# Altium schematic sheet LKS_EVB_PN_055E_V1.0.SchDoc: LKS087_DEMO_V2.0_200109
size A4; Revision: V1.0; SheetNumber: 1; SheetTotal: 1
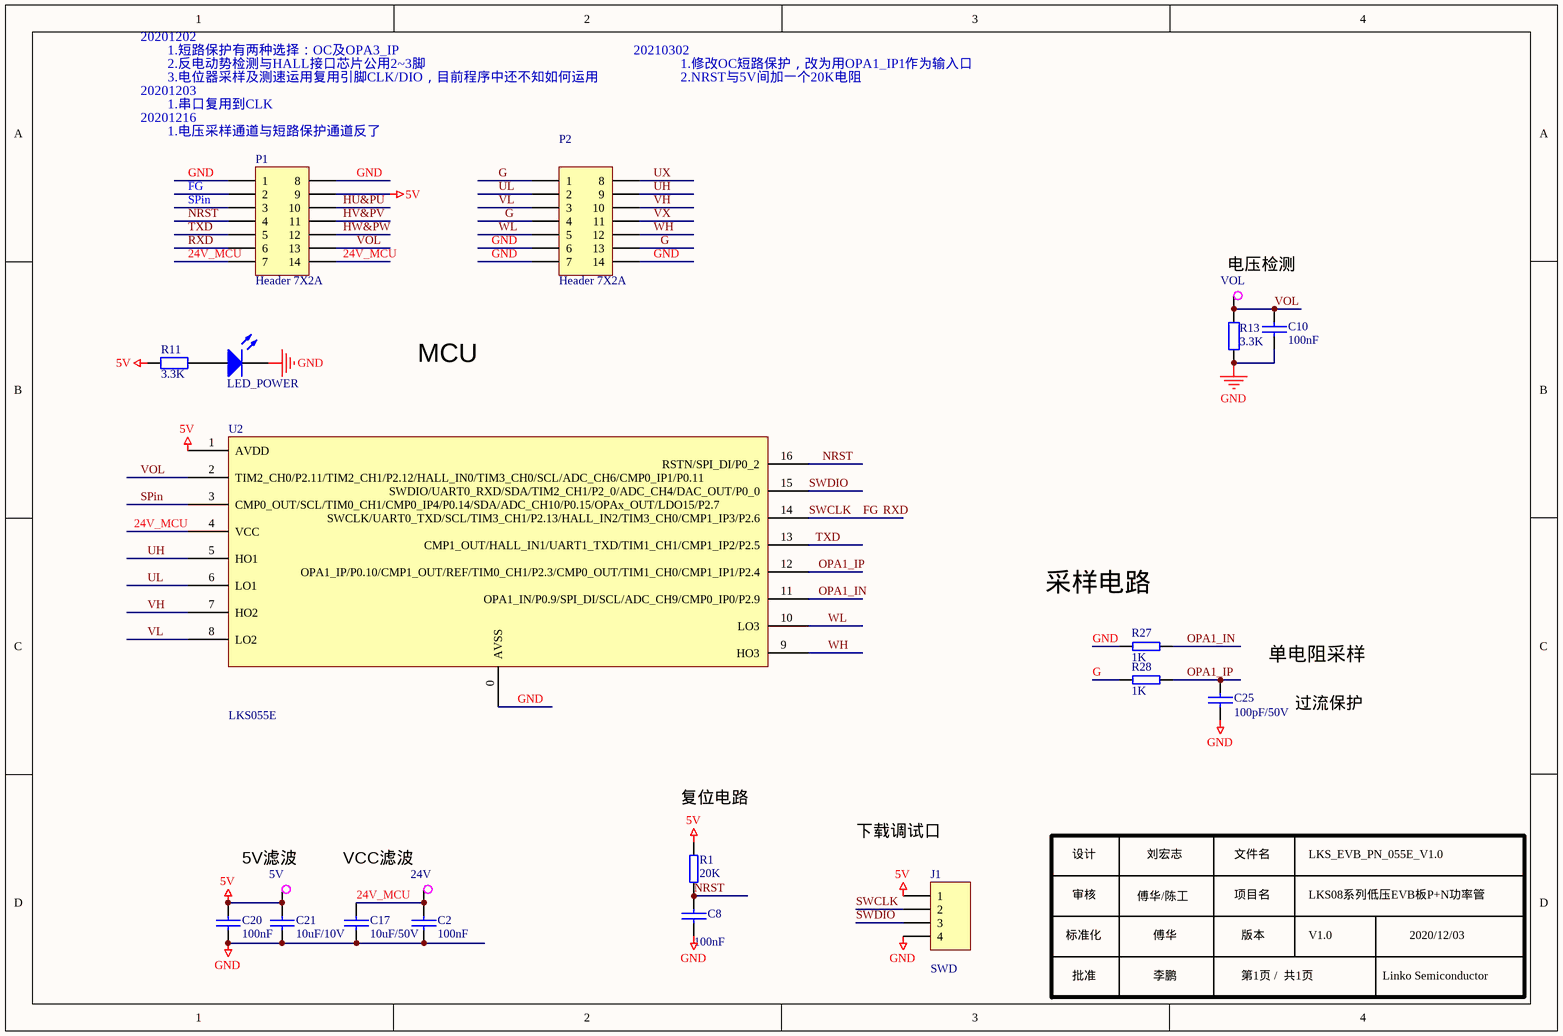
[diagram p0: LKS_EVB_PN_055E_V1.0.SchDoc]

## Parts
5V  TestP  [TP-80]  (value not drawn)
24V  TestP  [TP-80]  (value not drawn)
C2  100nF  [0805C]
C8  100nF  [0805C]
C10  100nF  [0805C]
C17  10uF/50V  [1206]
C20  100nF  [0805C]
C21  10uF/10V  [0805C]
C25  100pF/50V  [0805C]
J1  SWD  [SIP4-2.5]
LED_POWER  (no value)  [0805D]
P1  Header 7X2A  [HDR2X7_CEN]
P2  Header 7X2A  [HDR2X7_CEN]
R1  20K  [0805R]
R11  3.3K  [0603R]
R13  3.3K  [0805R]
R27  1K  [0805R]
R28  1K  [0805R]
U2  LKS055E  [PCBComponent_1]
VOL  TestP  [TP-80]  (value not drawn)

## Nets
5V: 5V.1 C20.1 C21.1 J1.1 P1.9 R1.1 R11.2 U2.1(AVDD)
GND: C2.2 C8.2 C10.2 C17.1 C20.2 C21.2 C25.1 J1.4 LED_POWER.2(K) P1.1 P1.8 P2.6 P2.7 P2.14 R13.2 R27.2 U2.0(AVSS)
24V_MCU: 24V.1 C2.1 C17.2 P1.7 P1.14 U2.4(VCC)
FG: J1.2 P1.2 P1.6 U2.14(SWCLK/UART0_TXD/SCL/TIM3_CH1/P2.13/HALL_IN2/TIM3_CH0/CMP1_IP3/P2.6)  [also labelled RXD, SWCLK]
G: P2.1 P2.4 P2.13 R28.2
HU&PU: P1.10
HV&PV: P1.11
HW&PW: P1.12
NRST: C8.1 P1.4 R1.2 U2.16(RSTN/SPI_DI/P0_2)
OPA1_IN: R27.1 U2.11(OPA1_IN/P0.9/SPI_DI/SCL/ADC_CH9/CMP0_IP0/P2.9)
OPA1_IP: C25.2 R28.1 U2.12(OPA1_IP/P0.10/CMP1_OUT/REF/TIM0_CH1/P2.3/CMP0_OUT/TIM1_CH0/CMP1_IP1/P2.4)
SPin: P1.3 U2.3(CMP0_OUT/SCL/TIM0_CH1/CMP0_IP4/P0.14/SDA/ADC_CH10/P0.15/OPAx_OUT/LDO15/P2.7)
SWDIO: J1.3 U2.15(SWDIO/UART0_RXD/SDA/TIM2_CH1/P2_0/ADC_CH4/DAC_OUT/P0_0)
TXD: P1.5 U2.13(CMP1_OUT/HALL_IN1/UART1_TXD/TIM1_CH1/CMP1_IP2/P2.5)
UH: P2.9 U2.5(HO1)
UL: P2.2 U2.6(LO1)
UX: P2.8
VH: P2.10 U2.7(HO2)
VL: P2.3 U2.8(LO2)
VOL: C10.1 P1.13 R13.1 U2.2(TIM2_CH0/P2.11/TIM2_CH1/P2.12/HALL_IN0/TIM3_CH0/SCL/ADC_CH6/CMP0_IP1/P0.11) VOL.1
VX: P2.11
WH: P2.12 U2.9(HO3)
WL: P2.5 U2.10(LO3)
NetLED_POWER_1: LED_POWER.1(A) R11.1

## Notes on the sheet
- 20201202
- 20201203
- 1.短路保护有两种选择：OC及OPA3_IP
- 2.反电动势检测与HALL接口芯片公用2~3脚
- 3.电位器采样及测速运用复用引脚CLK/DIO，目前程序中还不知如何运用
- 1.串口复用到CLK
- 20210302
- 1.修改OC短路保护，改为用OPA1_IP1作为输入口
- 2.NRST与5V间加一个20K电阻
- 20201216
- (near P1) 1.电压采样通道与短路保护通道反了
- MCU
- 采样电路
- 过流保护
- (near R1) 复位电路
- (near 5V) 5V滤波
- VCC滤波
- 设计
- 审核
- 傅华/陈工
- 刘宏志
- 文件名
- 项目名
- LKS_EVB_PN_055E_V1.0
- LKS08系列低压EVB板P+N功率管
- 标准化
- 批准
- 傅华
- 李鹏
- 版本
- 第1页 /  共1页
- V1.0
- Linko Semiconductor
- 2020/12/03
- Labels drawn without touching a wire or pin: 下载调试口, 单电阻采样, 电压检测

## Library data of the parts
C2 C10 C17 = CAP: Capacitor
C8 C20 C21 C25 = C: Capacitor
J1 = Header 4: Header, 4-Pin
LED_POWER = LED2: Typical RED, GREEN, YELLOW, AMBER GaAs LED
P1 P2 = Header 7X2A: Header, 7-Pin, Dual row
R1 R27 R28 = RES2-1
R11 R13 = Res2: Resistor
